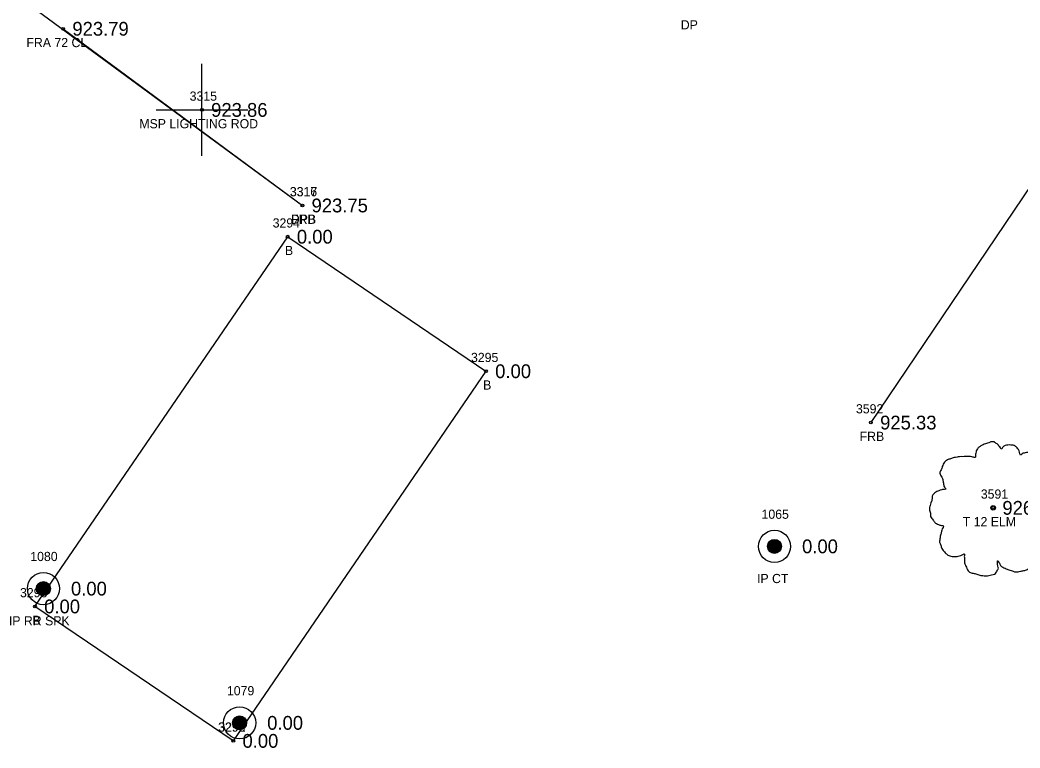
# Model space of a CAD drawing. Extents: x 1575382 to 1578175, y 1099175 to 1101955.
# Drawn here: x 1577214.1 to 1577323, y 1100868 to 1100947.2 of the extents above; entities that cross this region are included whole.
import ezdxf

# ---------------------------------------------------------------- set-up
doc = ezdxf.new("R2010")
doc.units = 0
for name, color, linetype in [('RD_EX_Bldg', 7, 'Continuous'), ('RD_EX_Bldg_txCode', 7, 'Continuous'), ('RD_EX_Driveway', 7, 'Continuous'), ('RD_EX_Driveway_txCode', 7, 'Continuous'), ('RD_EX_DV_Prop_txCode', 7, 'Continuous'), ('RD_EX_DV_PropPin', 7, 'Continuous'), ('RD_EX_Fence_Other', 7, 'Continuous'), ('RD_EX_Fence_Other_txCode', 7, 'Continuous'), ('RD_EX_Misc', 7, 'Continuous'), ('RD_EX_Misc_txCode', 7, 'Continuous'), ('RD_EX_TX_Bldg_ELEV', 7, 'Continuous'), ('RD_EX_TX_Driveway_ELEV', 7, 'Continuous'), ('RD_EX_TX_DV_Prop_ELEV', 7, 'Continuous'), ('RD_EX_TX_Fence_Other_ELEV', 7, 'Continuous'), ('RD_EX_TX_Misc_ELEV', 7, 'Continuous'), ('RD_EX_TX_VEG_ELEV', 7, 'Continuous'), ('RD_EX_VEG', 7, 'Continuous'), ('RD_EX_VEG_txCode', 7, 'Continuous'), ('RD_SMD_Locator', 7, 'Continuous')]:
    doc.layers.add(name, color=color, linetype=linetype)

msp = doc.modelspace()

# ---------------------------------------------------------------- linework, layer by layer
at = {"layer": 'RD_EX_Bldg'}
msp.add_lwpolyline([(1577237.33, 1100868.76), (1577215.74, 1100883.39), (1577243.25, 1100923.63), (1577264.84, 1100908.99), (1577237.33, 1100868.76)], dxfattribs=at)
at = {"layer": 'RD_EX_Driveway'}
msp.add_lwpolyline([(1577197.44, 1100946.62), (1577210.61, 1100952.2), (1577244.85, 1100927.03)], dxfattribs=at)
at = {"layer": 'RD_EX_DV_PropPin'}
for p, q in [((1577295.55, 1100889.63), (1577295.55, 1100890.23)), ((1577295.59, 1100889.56), (1577295.59, 1100890.3)), ((1577295.62, 1100889.5), (1577295.62, 1100890.35)), ((1577295.66, 1100889.45), (1577295.66, 1100890.4)), ((1577295.69, 1100889.41), (1577295.69, 1100890.44)), ((1577295.73, 1100889.38), (1577295.73, 1100890.48)), ((1577295.76, 1100889.35), (1577295.76, 1100890.51)), ((1577295.8, 1100889.32), (1577295.8, 1100890.54)), ((1577295.83, 1100889.29), (1577295.83, 1100890.56)), ((1577295.87, 1100889.27), (1577295.87, 1100890.58)), ((1577295.9, 1100889.25), (1577295.9, 1100890.6)), ((1577295.94, 1100889.23), (1577295.94, 1100890.62)), ((1577295.97, 1100889.22), (1577295.97, 1100890.64)), ((1577296.01, 1100889.21), (1577296.01, 1100890.65)), ((1577296.04, 1100889.2), (1577296.04, 1100890.66)), ((1577296.08, 1100889.19), (1577296.08, 1100890.67)), ((1577296.11, 1100889.18), (1577296.11, 1100890.68)), ((1577296.15, 1100889.17), (1577296.15, 1100890.68)), ((1577296.18, 1100889.17), (1577296.18, 1100890.69)), ((1577296.22, 1100889.17), (1577296.22, 1100890.69)), ((1577296.25, 1100889.17), (1577296.25, 1100890.69)), ((1577296.29, 1100889.17), (1577296.29, 1100890.69)), ((1577296.32, 1100889.17), (1577296.32, 1100890.69)), ((1577296.36, 1100889.17), (1577296.36, 1100890.68)), ((1577296.39, 1100889.18), (1577296.39, 1100890.68)), ((1577296.43, 1100889.19), (1577296.43, 1100890.67)), ((1577296.46, 1100889.2), (1577296.46, 1100890.66)), ((1577296.5, 1100889.21), (1577296.5, 1100890.65)), ((1577296.53, 1100889.22), (1577296.53, 1100890.64)), ((1577296.57, 1100889.23), (1577296.57, 1100890.62)), ((1577296.6, 1100889.25), (1577296.6, 1100890.6)), ((1577296.64, 1100889.27), (1577296.64, 1100890.58)), ((1577296.67, 1100889.29), (1577296.67, 1100890.56)), ((1577296.71, 1100889.32), (1577296.71, 1100890.54)), ((1577296.74, 1100889.35), (1577296.74, 1100890.51)), ((1577296.78, 1100889.38), (1577296.78, 1100890.48)), ((1577296.81, 1100889.41), (1577296.81, 1100890.44)), ((1577296.85, 1100889.45), (1577296.85, 1100890.4)), ((1577296.88, 1100889.5), (1577296.88, 1100890.35)), ((1577296.92, 1100889.56), (1577296.92, 1100890.3)), ((1577296.95, 1100889.63), (1577296.95, 1100890.23)), ((1577295.52, 1100889.73), (1577295.52, 1100890.12)), ((1577296.99, 1100889.73), (1577296.99, 1100890.12)), ((1577216.1, 1100884.81), (1577216.1, 1100885.84)), ((1577216.13, 1100884.77), (1577216.13, 1100885.88)), ((1577216.17, 1100884.74), (1577216.17, 1100885.91)), ((1577216.2, 1100884.72), (1577216.2, 1100885.94)), ((1577216.24, 1100884.69), (1577216.24, 1100885.96)), ((1577216.27, 1100884.67), (1577216.27, 1100885.98)), ((1577216.31, 1100884.65), (1577216.31, 1100886)), ((1577216.34, 1100884.63), (1577216.34, 1100886.02)), ((1577216.38, 1100884.62), (1577216.38, 1100886.03)), ((1577216.41, 1100884.61), (1577216.41, 1100886.05)), ((1577216.45, 1100884.59), (1577216.45, 1100886.06)), ((1577216.48, 1100884.58), (1577216.48, 1100886.07)), ((1577216.52, 1100884.58), (1577216.52, 1100886.07)), ((1577216.55, 1100884.57), (1577216.55, 1100886.08)), ((1577216.59, 1100884.57), (1577216.59, 1100886.08)), ((1577216.62, 1100884.57), (1577216.62, 1100886.09)), ((1577216.66, 1100884.56), (1577216.66, 1100886.09)), ((1577216.69, 1100884.57), (1577216.69, 1100886.09)), ((1577216.73, 1100884.57), (1577216.73, 1100886.08)), ((1577216.76, 1100884.57), (1577216.76, 1100886.08)), ((1577216.8, 1100884.58), (1577216.8, 1100886.07)), ((1577216.83, 1100884.58), (1577216.83, 1100886.07)), ((1577216.87, 1100884.59), (1577216.87, 1100886.06)), ((1577216.9, 1100884.61), (1577216.9, 1100886.05)), ((1577216.94, 1100884.62), (1577216.94, 1100886.03)), ((1577216.97, 1100884.63), (1577216.97, 1100886.02)), ((1577217.01, 1100884.65), (1577217.01, 1100886)), ((1577217.04, 1100884.67), (1577217.04, 1100885.98)), ((1577217.08, 1100884.69), (1577217.08, 1100885.96)), ((1577217.11, 1100884.72), (1577217.11, 1100885.94)), ((1577217.15, 1100884.74), (1577217.15, 1100885.91)), ((1577217.18, 1100884.77), (1577217.18, 1100885.88)), ((1577217.22, 1100884.81), (1577217.22, 1100885.84)), ((1577215.92, 1100885.13), (1577215.92, 1100885.52)), ((1577215.96, 1100885.03), (1577215.96, 1100885.62)), ((1577215.99, 1100884.96), (1577215.99, 1100885.7)), ((1577216.03, 1100884.9), (1577216.03, 1100885.75)), ((1577216.06, 1100884.85), (1577216.06, 1100885.8)), ((1577217.25, 1100884.85), (1577217.25, 1100885.8)), ((1577217.29, 1100884.9), (1577217.29, 1100885.75)), ((1577217.32, 1100884.96), (1577217.32, 1100885.7)), ((1577217.36, 1100885.03), (1577217.36, 1100885.62)), ((1577217.39, 1100885.13), (1577217.39, 1100885.52)), ((1577237.29, 1100870.52), (1577237.29, 1100870.91)), ((1577237.32, 1100870.42), (1577237.32, 1100871.02)), ((1577237.36, 1100870.35), (1577237.36, 1100871.09)), ((1577237.39, 1100870.29), (1577237.39, 1100871.14)), ((1577237.43, 1100870.24), (1577237.43, 1100871.19)), ((1577237.46, 1100870.2), (1577237.46, 1100871.23)), ((1577237.5, 1100870.17), (1577237.5, 1100871.27)), ((1577237.53, 1100870.14), (1577237.53, 1100871.3)), ((1577237.57, 1100870.11), (1577237.57, 1100871.33)), ((1577237.6, 1100870.08), (1577237.6, 1100871.35)), ((1577237.64, 1100870.06), (1577237.64, 1100871.37)), ((1577237.67, 1100870.04), (1577237.67, 1100871.39)), ((1577237.71, 1100870.03), (1577237.71, 1100871.41)), ((1577237.74, 1100870.01), (1577237.74, 1100871.43)), ((1577237.78, 1100870), (1577237.78, 1100871.44)), ((1577237.81, 1100869.99), (1577237.81, 1100871.45)), ((1577237.85, 1100869.98), (1577237.85, 1100871.46)), ((1577237.88, 1100869.97), (1577237.88, 1100871.47)), ((1577237.92, 1100869.96), (1577237.92, 1100871.47)), ((1577237.95, 1100869.96), (1577237.95, 1100871.48)), ((1577237.99, 1100869.96), (1577237.99, 1100871.48)), ((1577238.02, 1100869.96), (1577238.02, 1100871.48)), ((1577238.06, 1100869.96), (1577238.06, 1100871.48)), ((1577238.09, 1100869.96), (1577238.09, 1100871.48)), ((1577238.13, 1100869.96), (1577238.13, 1100871.47)), ((1577238.16, 1100869.97), (1577238.16, 1100871.47)), ((1577238.2, 1100869.98), (1577238.2, 1100871.46)), ((1577238.23, 1100869.99), (1577238.23, 1100871.45)), ((1577238.27, 1100870), (1577238.27, 1100871.44)), ((1577238.3, 1100870.01), (1577238.3, 1100871.43)), ((1577238.34, 1100870.03), (1577238.34, 1100871.41)), ((1577238.37, 1100870.04), (1577238.37, 1100871.39)), ((1577238.41, 1100870.06), (1577238.41, 1100871.37)), ((1577238.44, 1100870.08), (1577238.44, 1100871.35)), ((1577238.48, 1100870.11), (1577238.48, 1100871.33)), ((1577238.51, 1100870.14), (1577238.51, 1100871.3)), ((1577238.55, 1100870.17), (1577238.55, 1100871.27)), ((1577238.58, 1100870.2), (1577238.58, 1100871.23)), ((1577238.62, 1100870.24), (1577238.62, 1100871.19)), ((1577238.65, 1100870.29), (1577238.65, 1100871.14)), ((1577238.69, 1100870.35), (1577238.69, 1100871.09)), ((1577238.72, 1100870.42), (1577238.72, 1100871.02)), ((1577238.76, 1100870.52), (1577238.76, 1100870.91))]:
    msp.add_line(p, q, dxfattribs=at)
for centre, radius in [((1577296.25, 1100889.93), 1.75), ((1577296.25, 1100889.93), 0.761), ((1577216.66, 1100885.33), 1.75), ((1577216.66, 1100885.33), 0.761), ((1577238.02, 1100870.72), 1.75), ((1577238.02, 1100870.72), 0.761)]:
    msp.add_circle(centre, radius, dxfattribs=at)
at = {"layer": 'RD_EX_Fence_Other'}
msp.add_line((1577218.81, 1100946.26), (1577244.85, 1100927.03), dxfattribs=at)
msp.add_lwpolyline([(1577327.05, 1100968.06), (1577342.76, 1100956.82), (1577306.75, 1100903.4)], dxfattribs=at)
at = {"layer": 'RD_EX_Misc'}
for p, q in [((1577233.92, 1100932.43), (1577233.92, 1100942.43)), ((1577228.92, 1100937.43), (1577238.92, 1100937.43))]:
    msp.add_line(p, q, dxfattribs=at)
at = {"layer": 'RD_EX_VEG'}
for centre, radius in [((1577320.06, 1100894.12), 0.25), ((1577320.05, 1100894.1), 0.0001)]:
    msp.add_circle(centre, radius, dxfattribs=at)
for points in [[(1577320.19, 1100901.29), (1577319.89, 1100901.31), (1577319.57, 1100901.21), (1577319.32, 1100901.11), (1577319.09, 1100901.04), (1577318.87, 1100900.94), (1577318.57, 1100900.76), (1577318.34, 1100900.56), (1577318.22, 1100900.31), (1577318.17, 1100900.09), (1577318.12, 1100899.81), (1577318.12, 1100899.64), (1577317.99, 1100899.61), (1577317.84, 1100899.64), (1577317.59, 1100899.71), (1577317.34, 1100899.71), (1577317.09, 1100899.71), (1577316.74, 1100899.69), (1577316.39, 1100899.69), (1577316.12, 1100899.64), (1577315.8, 1100899.59), (1577315.42, 1100899.46), (1577315.07, 1100899.34), (1577314.77, 1100899.09), (1577314.52, 1100898.61), (1577314.4, 1100898.26), (1577314.25, 1100898.01), (1577314.4, 1100897.56), (1577314.57, 1100897.21), (1577314.6, 1100897.01), (1577314.67, 1100896.59), (1577314.77, 1100896.36), (1577314.9, 1100896.16), (1577314.82, 1100896.14), (1577314.45, 1100896.09), (1577314.15, 1100895.99), (1577313.72, 1100895.76), (1577313.5, 1100895.54), (1577313.4, 1100895.21), (1577313.37, 1100894.86), (1577313.27, 1100894.66), (1577313.2, 1100894.39), (1577313.17, 1100894.31), (1577313.12, 1100893.99), (1577313.22, 1100893.54), (1577313.25, 1100893.19), (1577313.37, 1100892.96), (1577313.52, 1100892.79), (1577313.7, 1100892.54), (1577314.1, 1100892.31), (1577314.42, 1100892.21), (1577314.62, 1100892.19), (1577314.45, 1100891.69), (1577314.4, 1100891.34), (1577314.27, 1100890.94), (1577314.27, 1100890.86), (1577314.22, 1100890.39), (1577314.37, 1100890.06), (1577314.45, 1100889.69), (1577314.62, 1100889.47), (1577314.9, 1100889.17), (1577315.22, 1100888.94), (1577315.72, 1100888.82), (1577316.12, 1100888.84), (1577316.69, 1100889.02), (1577316.94, 1100889.09), (1577316.92, 1100888.92), (1577316.94, 1100888.54), (1577316.94, 1100888.12), (1577317.09, 1100887.79), (1577317.19, 1100887.52), (1577317.34, 1100887.27), (1577317.67, 1100887.04), (1577318.07, 1100886.97), (1577318.49, 1100886.82), (1577318.94, 1100886.74), (1577319.44, 1100886.72), (1577320.04, 1100886.87), (1577320.32, 1100886.99), (1577320.42, 1100887.17), (1577320.62, 1100887.54), (1577320.57, 1100887.77), (1577320.59, 1100888.37), (1577320.69, 1100888.19), (1577320.87, 1100887.84), (1577321.37, 1100887.54), (1577321.77, 1100887.37), (1577322.24, 1100887.22), (1577322.54, 1100887.14), (1577323.02, 1100887.22), (1577323.39, 1100887.29), (1577323.77, 1100887.42), (1577324.07, 1100887.69), (1577324.24, 1100887.97), (1577324.29, 1100888.24), (1577324.37, 1100888.62), (1577324.42, 1100888.79)], [(1577324.42, 1100888.79), (1577324.34, 1100888.97), (1577324.29, 1100889.22), (1577324.37, 1100889.19), (1577324.54, 1100889.14), (1577324.82, 1100889.02), (1577325.04, 1100888.94), (1577325.37, 1100888.97), (1577325.64, 1100889.07), (1577326.09, 1100889.34), (1577326.37, 1100889.82), (1577326.64, 1100890.21), (1577326.72, 1100890.54), (1577326.67, 1100890.76), (1577326.64, 1100891.26), (1577326.44, 1100891.51), (1577326.39, 1100891.64), (1577326.29, 1100892.04), (1577326.37, 1100892.09), (1577326.64, 1100892.14), (1577327.02, 1100892.26), (1577327.29, 1100892.39), (1577327.52, 1100892.56), (1577327.59, 1100892.79), (1577327.57, 1100893.19), (1577327.61, 1100893.59), (1577327.54, 1100893.74), (1577327.44, 1100893.89), (1577327.37, 1100894.09), (1577327.22, 1100894.24), (1577327.12, 1100894.39), (1577327.02, 1100894.49), (1577326.89, 1100894.64), (1577326.72, 1100894.76), (1577326.57, 1100894.81), (1577326.52, 1100894.96), (1577326.67, 1100895.16), (1577326.72, 1100895.26), (1577326.74, 1100895.49), (1577326.97, 1100895.84), (1577327.02, 1100896.24), (1577326.97, 1100896.66), (1577326.92, 1100896.94), (1577326.77, 1100897.21), (1577326.57, 1100897.46), (1577326.44, 1100897.64), (1577326.27, 1100897.76), (1577325.94, 1100897.89), (1577325.69, 1100897.94), (1577325.34, 1100897.94), (1577325.14, 1100897.99), (1577325.17, 1100898.04), (1577325.17, 1100898.19), (1577325.17, 1100898.46), (1577325.09, 1100898.91), (1577324.94, 1100899.41), (1577324.94, 1100899.44), (1577324.84, 1100899.69), (1577324.62, 1100899.89), (1577324.44, 1100899.99), (1577324.24, 1100900.11), (1577323.99, 1100900.14), (1577323.69, 1100900.14), (1577323.42, 1100900.09), (1577323.22, 1100899.99), (1577323.04, 1100899.86), (1577322.97, 1100900.01), (1577322.87, 1100900.31), (1577322.82, 1100900.46), (1577322.67, 1100900.64), (1577322.44, 1100900.84), (1577321.99, 1100900.96), (1577321.37, 1100900.89), (1577321.07, 1100900.69), (1577320.92, 1100900.51), (1577320.87, 1100900.64), (1577320.67, 1100900.84), (1577320.57, 1100901.01), (1577320.39, 1100901.14), (1577320.24, 1100901.24), (1577320.14, 1100901.29)]]:
    msp.add_spline(points, degree=3, dxfattribs=at)
at = {"layer": 'RD_SMD_Locator'}
for centre in [(1577218.81, 1100946.26), (1577233.92, 1100937.43), (1577244.85, 1100927.03), (1577244.85, 1100927.03), (1577243.25, 1100923.63), (1577264.84, 1100908.99), (1577306.75, 1100903.4), (1577320.06, 1100894.12), (1577296.25, 1100889.93), (1577216.66, 1100885.33), (1577215.74, 1100883.39), (1577238.02, 1100870.72), (1577237.33, 1100868.76), (1577237.33, 1100868.76)]:
    msp.add_circle(centre, 0.15, dxfattribs=at)

# ---------------------------------------------------------------- texts
at = {"layer": 'RD_EX_Bldg_txCode'}
for s, p in [('3294', (1577241.62, 1100924.63)), ('B', (1577242.95, 1100921.63)), ('3295', (1577263.21, 1100909.99)), ('B', (1577264.53, 1100906.99)), ('3293', (1577214.11, 1100884.39)), ('B', (1577215.44, 1100881.39)), ('3296', (1577235.67, 1100869.76)), ('3292', (1577235.7, 1100869.76))]:
    msp.add_text(s, height=1, dxfattribs=at).set_placement(p)
at = {"layer": 'RD_EX_Driveway_txCode'}
for s, p in [('DP', (1577286.05, 1100946.19)), ('3317', (1577243.5, 1100928.03)), ('DPB', (1577243.6, 1100925.03))]:
    msp.add_text(s, height=1, dxfattribs=at).set_placement(p)
at = {"layer": 'RD_EX_DV_Prop_txCode'}
for s, p in [('1065', (1577294.84, 1100892.93)), ('1080', (1577215.23, 1100888.33)), ('IP CT', (1577294.35, 1100885.93)), ('IP RR SPK', (1577212.9, 1100881.33)), ('1079', (1577236.64, 1100873.72))]:
    msp.add_text(s, height=1, dxfattribs=at).set_placement(p)
at = {"layer": 'RD_EX_Fence_Other_txCode'}
for s, p in [('FRA 72 CL', (1577214.81, 1100944.26)), ('3316', (1577243.48, 1100928.03)), ('FRB', (1577243.62, 1100925.03)), ('3592', (1577305.12, 1100904.4)), ('FRB', (1577305.52, 1100901.4))]:
    msp.add_text(s, height=1, dxfattribs=at).set_placement(p)
at = {"layer": 'RD_EX_Misc_txCode'}
for s, p in [('3315', (1577232.58, 1100938.43)), ('MSP LIGHTING ROD', (1577227.1, 1100935.43))]:
    msp.add_text(s, height=1, dxfattribs=at).set_placement(p)
at = {"layer": 'RD_EX_TX_Bldg_ELEV'}
for p in [(1577244.25, 1100922.88), (1577265.84, 1100908.24), (1577216.74, 1100882.64), (1577238.33, 1100868.01), (1577238.33, 1100868.01)]:
    msp.add_text('0.00', height=1.5, dxfattribs=at).set_placement(p)
at = {"layer": 'RD_EX_TX_Driveway_ELEV'}
msp.add_text('923.75', height=1.5, dxfattribs=at).set_placement((1577245.85, 1100926.28))
at = {"layer": 'RD_EX_TX_DV_Prop_ELEV'}
for p in [(1577299.25, 1100889.18), (1577219.66, 1100884.58), (1577241.02, 1100869.97)]:
    msp.add_text('0.00', height=1.5, dxfattribs=at).set_placement(p)
at = {"layer": 'RD_EX_TX_Fence_Other_ELEV'}
for s, p in [('923.79', (1577219.81, 1100945.51)), ('923.75', (1577245.85, 1100926.28)), ('925.33', (1577307.75, 1100902.65))]:
    msp.add_text(s, height=1.5, dxfattribs=at).set_placement(p)
at = {"layer": 'RD_EX_TX_Misc_ELEV'}
msp.add_text('923.86', height=1.5, dxfattribs=at).set_placement((1577234.92, 1100936.68))
at = {"layer": 'RD_EX_TX_VEG_ELEV'}
msp.add_text('926.86', height=1.5, dxfattribs=at).set_placement((1577321.06, 1100893.37))
at = {"layer": 'RD_EX_VEG_txCode'}
for s, p in [('3591', (1577318.71, 1100895.12)), ('T 12 ELM', (1577316.75, 1100892.12))]:
    msp.add_text(s, height=1, dxfattribs=at).set_placement(p)

doc.saveas('drawing.dxf')
